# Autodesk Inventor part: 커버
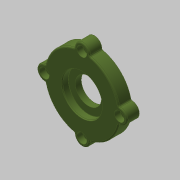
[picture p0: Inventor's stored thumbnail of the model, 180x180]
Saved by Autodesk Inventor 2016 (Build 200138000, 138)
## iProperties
Created: 2016-06
Part Number: 커버
Material: 알루미늄 6061
Document SubType Name: Modeling
Designer: mduedu
Density: 2.71 g/cm^3
Appearance: 올리브 녹색
Mass: 67.5462 g
Surface Area: 95.1118 cm^2
Volume: 24.9248 cm^3
Author: mduedu
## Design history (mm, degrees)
sketch "스케치1"
  geometry: C1 r 30 at (0, 0); 1 further point
  constraints: 1 centre point, 1 coincident
  dimensions: "d0" = 60 diameter of C1
extrude "돌출1" new body sketch "스케치1" distance "d2" = 10; taper "d3" = 0 deg
sketch "스케치5"
  geometry: C1 r 6 at (0, 30); 2 further points
  constraints: 2 vertical alignment, 1 centre point, 1 other
  dimensions: "d61" = 12 diameter of C1
extrude "돌출3" join sketch "스케치5" stored distance "d62" = 10; taper "d63" = 0 deg
sketch "스케치2"
  geometry: C1 r 21 at (0, 0); 1 further point
  constraints: 1 centre point, 1 coincident
  dimensions: "d4" = 42 diameter of C1
extrude "돌출2" join sketch "스케치2" distance "d6" = 3; taper "d7" = 0 deg
hole "구멍1" diameter "d11" = 35; stored, may be unused: countersink angle "d15" = 90 deg, drill point angle "d17" = 0 deg; dims "d9" = 10, "d10" = 10, "d12" = 6, "d13" = 4, "d14" = 2, "d16" = 3
hole "구멍2" diameter "d20" = 32; stored, may be unused: countersink angle "d24" = 90 deg, drill point angle "d26" = 0 deg; dims "d21" = 6, "d22" = 4, "d23" = 2, "d25" = 5.2, "d67" = 10, "d68" = 10
hole "구멍3" diameter "d29" = 21; stored, may be unused: countersink angle "d33" = 90 deg, drill point angle "d35" = 0 deg; dims "d27" = 10, "d28" = 10, "d30" = 6, "d31" = 4, "d32" = 2, "d34" = 5
fillet "모깎기2" dims "d36" = 3
fillet "모깎기3" dims "d37" = 0.1
chamfer "모따기1" distance "d38" = 0.75; stored, may be unused: second distance "d39" = 2, angle "d40" = 30 deg
chamfer "모따기2" distance "d42" = 0.5; stored, may be unused: second distance "d43" = 2, angle "d44" = 30 deg
sketch "스케치6"
  geometry: A1 r 30 centre (0, 0) between (29.4, 5.97) and (5.97, 29.4) reference; 3 further points
  constraints: 2 vertical alignment, 1 coincident, 3 other
hole "구멍5" sketch "스케치6" at (0, 30) diameter "d69" = 4.5; stored, may be unused: countersink angle "d73" = 90 deg, drill point angle "d75" = 118 deg; dims "d70" = 6, "d71" = 8, "d72" = 4.6, "d74" = 8
fillet "모깎기5" dims "d79" = 1
fillet "모깎기6" dims "d80" = 1
node "솔리드1"
pattern_circular "원형 패턴1" dims angle "d65" = 360 deg
pattern_circular "원형 패턴2" dims angle "d77" = 360 deg
node "투영된 루프1"
